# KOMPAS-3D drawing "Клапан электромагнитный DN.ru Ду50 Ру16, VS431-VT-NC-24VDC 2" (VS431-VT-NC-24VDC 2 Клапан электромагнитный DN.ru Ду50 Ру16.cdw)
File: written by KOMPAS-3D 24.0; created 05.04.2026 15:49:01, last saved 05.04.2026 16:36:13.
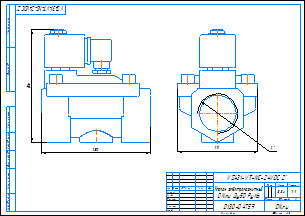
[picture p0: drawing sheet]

Document properties: c3d_UniqueCompID: ef56311e-7521-43dc-8291-0e6108b3d81d; Автор: artio; Класс точности: c; Знак неуказанной шероховатости: Шероховатость не задана; Рассекать на разрезах: Да; c3d_UniqueCompID: ef56311e-7521-43dc-8291-0e6108b3d81d; Автор: artio; Класс точности: c; Знак неуказанной шероховатости: Шероховатость не задана; Рассекать на разрезах: Да; c3d_UniqueCompID: ef56311e-7521-43dc-8291-0e6108b3d81d; Автор: artio; Класс точности: c; Знак неуказанной шероховатости: Шероховатость не задана; Рассекать на разрезах: Да; c3d_UniqueCompID: ef56311e-7521-43dc-8291-0e6108b3d81d; Автор: artio; Класс точности: c; Знак неуказанной шероховатости: Шероховатость не задана; Рассекать на разрезах: Да; c3d_UniqueCompID: ef56311e-7521-43dc-8291-0e6108b3d81d; Автор: artio; Класс точности: c; Знак неуказанной шероховатости: Шероховатость не задана; Рассекать на разрезах: Да; Автор: artio; Форматы листов документа: A3; Полное имя файла: VS431-VT-NC-24VDC 2 Клапан электромагнитный DN.ru Ду50 Ру16.m3d; Масса: 3.341; Наименование: Клапан электромагнитный DN.ru Ду50 Ру16; Количество листов документа: 1; Примечание: D130-04759

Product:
- Body: Тело 1  | qty 1
    Масса: 6.703651
- Part/product: Клапан электромагнитный DN.ru Ду50 Ру16  | designation VS431-VT-NC-24VDC 2
    Масса: 3.341
    Раздел спецификации: Прочие изделия
    Примечание: D130-04759
    additional columns: ef56311e-7521-43dc-8291-0e6108b3d81d; artio; c; Шероховатость не задана; Да

Views: Вид 1, Спереди
Referenced files in C:\Users\artio\OneDrive\Рабочий стол\Клапан электромагнитный DN.ru\VS431\VS431-ET-NC\: VS431-ET-NC-24VDC 3-4 Клапан электромагнитный DN.ru Ду20 Ру16.m3d, VS431-ET-NC-24VDC 3-4 Клапан электромагнитный DN.ru Ду20 Ру16.cdw
Referenced files in C:\Users\artio\OneDrive\Рабочий стол\Клапан электромагнитный DN.ru\VS431\VS431-VT-NC\: VS431-VT-NC-24VDC 2 Клапан электромагнитный DN.ru Ду50 Ру16.m3d
Referenced files in C:\Users\artio\OneDrive\Рабочий стол\Клапан электромагнитный DN.ru\VS431\VS431-VT-NC\VS431-VT-NC-24VDC\Ду50\: VS431-VT-NC-24VDC 2 Клапан электромагнитный DN.ru Ду50 Ру16.m3d
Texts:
  VS431-VT-NC-24VDC 2
  Клапан электромагнитный
  DN.ru Ду50 Ру16
  VS431-VT-NC-24VDC 2"
  VS431-VT-NC-24VDC 2"-
  Клапан электромагнитный DN.ru Ду50 Ру16
  VS431-VT-NC-24VDC 2 Клапан электромагнитный DN.ru Ду50 Ру16
Dimensions and other numbers on the sheet: 0; 3; 2; 4; 111; 1:1; 1; 3,34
